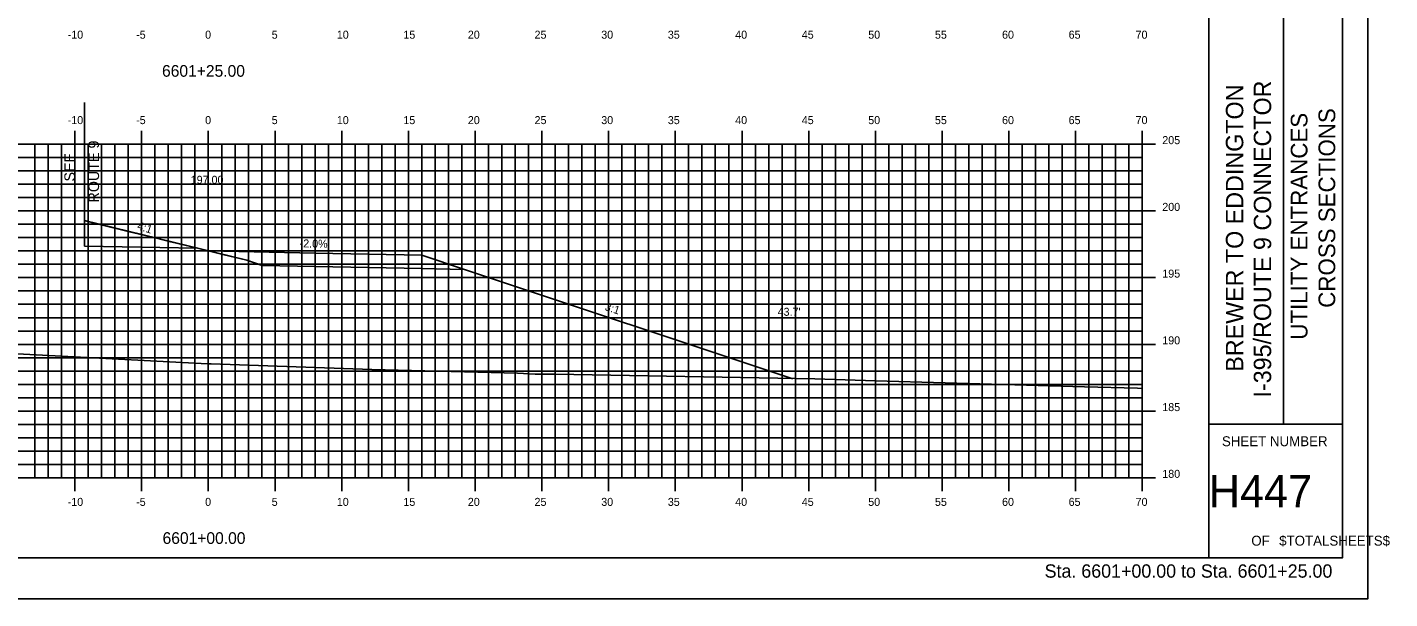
# Model space of a CAD drawing. Extents: x 1723518 to 1723690, y 459560 to 459670.
# Drawn here: x 1723587.4 to 1723689.5, y 459559.6 to 459602.4 of the extents above; entities that cross this region are included whole.
import ezdxf

# ---------------------------------------------------------------- set-up
doc = ezdxf.new("R2010")
doc.units = 0
for name, color, linetype in [('ANNOTATION', 7, 'Continuous'), ('BORDER', 7, 'Continuous'), ('D_Roadway_Centerline', 7, 'Continuous'), ('D_Roadway_Centerline_Text', 7, 'Continuous'), ('D_Roadway_Drive_Gravel', 7, 'Continuous'), ('D_Roadway_Edge_Shoulder', 7, 'Continuous'), ('D_Roadway_SlopeLines', 7, 'Continuous'), ('D_Roadway_SubGrade', 7, 'Continuous'), ('D_Text_Standard', 7, 'Continuous'), ('H_V ANNOTATION', 7, 'Continuous'), ('HIGHWAY_TITLE', 7, 'Continuous'), ('MAJOR', 7, 'Continuous'), ('MINOR', 7, 'Continuous'), ('PLOT BOUNDARY', 7, 'Continuous'), ('S_Roadway_Centerline', 7, 'Continuous')]:
    doc.layers.add(name, color=color, linetype=linetype)

msp = doc.modelspace()

# ---------------------------------------------------------------- linework, layer by layer
msp.add_lwpolyline([(1723600.95, 459585.61), (1723600.96, 459585.61), (1723608.96, 459585.45), (1723616.96, 459585.29), (1723620.15, 459584.23), (1723644.69, 459576.05), (1723644.72, 459576.05), (1723644.76, 459576.05), (1723644.77, 459576.04), (1723644.78, 459576.04)])
at = {"layer": 'BORDER'}
for p, q in [((1723675.96, 459562.61), (1723675.96, 459667.61)), ((1723681.55, 459572.62), (1723681.55, 459607.62)), ((1723675.96, 459572.62), (1723685.96, 459572.62))]:
    msp.add_line(p, q, dxfattribs=at)
msp.add_lwpolyline([(1723525.96, 459562.61), (1723685.96, 459562.61), (1723685.96, 459667.61), (1723525.96, 459667.61)], close=True, dxfattribs=at)
at = {"layer": 'D_Roadway_Centerline'}
msp.add_lwpolyline([(1723591.67, 459587.88), (1723592.32, 459587.72), (1723592.63, 459587.64), (1723595.06, 459587.05), (1723597, 459586.58), (1723598.15, 459586.3), (1723600.16, 459585.81), (1723602.05, 459585.35), (1723603.85, 459584.91), (1723603.97, 459584.87), (1723603.98, 459584.86), (1723605, 459584.53)], dxfattribs=at)
at = {"layer": 'D_Roadway_Drive_Gravel'}
msp.add_lwpolyline([(1723600.96, 459585.61), (1723608.96, 459585.45), (1723616.96, 459585.29), (1723620.15, 459584.23), (1723616.96, 459584.29), (1723608.96, 459584.45), (1723605, 459584.53)], dxfattribs=at)
at = {"layer": 'D_Roadway_Edge_Shoulder'}
msp.add_line((1723591.67, 459587.88), (1723591.67, 459587.63), dxfattribs=at)
msp.add_line((1723591.67, 459587.88), (1723591.67, 459587.63), dxfattribs=at)
at = {"layer": 'D_Roadway_SlopeLines'}
for points in [[(1723591.67, 459587.88), (1723603.85, 459584.91), (1723605, 459584.53)], [(1723591.67, 459587.88), (1723603.85, 459584.91), (1723605, 459584.53)], [(1723591.67, 459587.88), (1723603.85, 459584.91), (1723605, 459584.53)], [(1723591.67, 459587.88), (1723603.85, 459584.91), (1723605, 459584.53)], [(1723591.67, 459587.88), (1723603.85, 459584.91), (1723605, 459584.53)], [(1723591.67, 459587.88), (1723603.85, 459584.91), (1723605, 459584.53)], [(1723591.67, 459587.88), (1723603.85, 459584.91), (1723605, 459584.53)], [(1723616.96, 459585.29), (1723620.15, 459584.23), (1723644.69, 459576.05)]]:
    msp.add_lwpolyline(points, dxfattribs=at)
at = {"layer": 'D_Roadway_SubGrade'}
msp.add_line((1723591.67, 459596.74), (1723591.67, 459585.96), dxfattribs=at)
msp.add_lwpolyline([(1723591.67, 459587.63), (1723591.67, 459587.88), (1723600.16, 459585.81), (1723591.67, 459585.96)], dxfattribs=at)
msp.add_lwpolyline([(1723591.67, 459587.63), (1723591.67, 459587.88), (1723600.16, 459585.81), (1723591.67, 459585.96)], dxfattribs=at)
msp.add_lwpolyline([(1723591.67, 459587.63), (1723591.67, 459587.88), (1723600.16, 459585.81), (1723591.67, 459585.96)], dxfattribs=at)
msp.add_lwpolyline([(1723591.67, 459587.63), (1723591.67, 459587.88), (1723600.16, 459585.81), (1723591.67, 459585.96)], dxfattribs=at)
at = {"layer": 'MAJOR'}
for p, q in [((1723590.96, 459594.61), (1723590.96, 459593.61)), ((1723595.96, 459594.61), (1723595.96, 459593.61)), ((1723600.96, 459594.61), (1723600.96, 459593.61)), ((1723605.96, 459594.61), (1723605.96, 459593.61)), ((1723610.96, 459594.61), (1723610.96, 459593.61)), ((1723615.96, 459594.61), (1723615.96, 459593.61)), ((1723620.96, 459594.61), (1723620.96, 459593.61)), ((1723625.96, 459594.61), (1723625.96, 459593.61)), ((1723630.96, 459594.61), (1723630.96, 459593.61)), ((1723635.96, 459594.61), (1723635.96, 459593.61)), ((1723640.96, 459594.61), (1723640.96, 459593.61)), ((1723645.96, 459594.61), (1723645.96, 459593.61)), ((1723650.96, 459594.61), (1723650.96, 459593.61)), ((1723655.96, 459594.61), (1723655.96, 459593.61)), ((1723660.96, 459594.61), (1723660.96, 459593.61)), ((1723665.96, 459594.61), (1723665.96, 459593.61)), ((1723670.96, 459594.61), (1723670.96, 459593.61)), ((1723530.96, 459593.61), (1723670.96, 459593.61)), ((1723530.96, 459593.61), (1723670.96, 459593.61)), ((1723590.96, 459568.61), (1723590.96, 459593.61)), ((1723595.96, 459568.61), (1723595.96, 459593.61)), ((1723600.96, 459568.61), (1723600.96, 459593.61)), ((1723605.96, 459568.61), (1723605.96, 459593.61)), ((1723610.96, 459568.61), (1723610.96, 459593.61)), ((1723615.96, 459568.61), (1723615.96, 459593.61)), ((1723620.96, 459568.61), (1723620.96, 459593.61)), ((1723625.96, 459568.61), (1723625.96, 459593.61)), ((1723630.96, 459568.61), (1723630.96, 459593.61)), ((1723635.96, 459568.61), (1723635.96, 459593.61)), ((1723640.96, 459568.61), (1723640.96, 459593.61)), ((1723645.96, 459568.61), (1723645.96, 459593.61)), ((1723650.96, 459568.61), (1723650.96, 459593.61)), ((1723655.96, 459568.61), (1723655.96, 459593.61)), ((1723660.96, 459568.61), (1723660.96, 459593.61)), ((1723665.96, 459568.61), (1723665.96, 459593.61)), ((1723671.96, 459593.61), (1723669.96, 459593.61)), ((1723670.96, 459568.61), (1723670.96, 459593.61)), ((1723670.96, 459568.61), (1723670.96, 459593.61)), ((1723530.96, 459588.61), (1723670.96, 459588.61)), ((1723671.96, 459588.61), (1723669.96, 459588.61)), ((1723530.96, 459583.61), (1723670.96, 459583.61)), ((1723671.96, 459583.61), (1723669.96, 459583.61)), ((1723530.96, 459578.61), (1723670.96, 459578.61)), ((1723671.96, 459578.61), (1723669.96, 459578.61)), ((1723530.96, 459573.61), (1723670.96, 459573.61)), ((1723671.96, 459573.61), (1723669.96, 459573.61)), ((1723530.96, 459568.61), (1723670.96, 459568.61)), ((1723530.96, 459568.61), (1723670.96, 459568.61)), ((1723590.96, 459567.61), (1723590.96, 459568.61)), ((1723595.96, 459567.61), (1723595.96, 459568.61)), ((1723600.96, 459567.61), (1723600.96, 459568.61)), ((1723605.96, 459567.61), (1723605.96, 459568.61)), ((1723610.96, 459567.61), (1723610.96, 459568.61)), ((1723615.96, 459567.61), (1723615.96, 459568.61)), ((1723620.96, 459567.61), (1723620.96, 459568.61)), ((1723625.96, 459567.61), (1723625.96, 459568.61)), ((1723630.96, 459567.61), (1723630.96, 459568.61)), ((1723635.96, 459567.61), (1723635.96, 459568.61)), ((1723640.96, 459567.61), (1723640.96, 459568.61)), ((1723645.96, 459567.61), (1723645.96, 459568.61)), ((1723650.96, 459567.61), (1723650.96, 459568.61)), ((1723655.96, 459567.61), (1723655.96, 459568.61)), ((1723660.96, 459567.61), (1723660.96, 459568.61)), ((1723665.96, 459567.61), (1723665.96, 459568.61)), ((1723671.96, 459568.61), (1723669.96, 459568.61)), ((1723670.96, 459567.61), (1723670.96, 459568.61))]:
    msp.add_line(p, q, dxfattribs=at)
at = {"layer": 'MINOR'}
for p, q in [((1723587.96, 459568.61), (1723587.96, 459593.61)), ((1723588.96, 459568.61), (1723588.96, 459593.61)), ((1723589.96, 459568.61), (1723589.96, 459593.61)), ((1723591.96, 459568.61), (1723591.96, 459593.61)), ((1723592.96, 459568.61), (1723592.96, 459593.61)), ((1723593.96, 459568.61), (1723593.96, 459593.61)), ((1723594.96, 459568.61), (1723594.96, 459593.61)), ((1723596.96, 459568.61), (1723596.96, 459593.61)), ((1723597.96, 459568.61), (1723597.96, 459593.61)), ((1723598.96, 459568.61), (1723598.96, 459593.61)), ((1723599.96, 459568.61), (1723599.96, 459593.61)), ((1723601.96, 459568.61), (1723601.96, 459593.61)), ((1723602.96, 459568.61), (1723602.96, 459593.61)), ((1723603.96, 459568.61), (1723603.96, 459593.61)), ((1723604.96, 459568.61), (1723604.96, 459593.61)), ((1723606.96, 459568.61), (1723606.96, 459593.61)), ((1723607.96, 459568.61), (1723607.96, 459593.61)), ((1723608.96, 459568.61), (1723608.96, 459593.61)), ((1723609.96, 459568.61), (1723609.96, 459593.61)), ((1723611.96, 459568.61), (1723611.96, 459593.61)), ((1723612.96, 459568.61), (1723612.96, 459593.61)), ((1723613.96, 459568.61), (1723613.96, 459593.61)), ((1723614.96, 459568.61), (1723614.96, 459593.61)), ((1723616.96, 459568.61), (1723616.96, 459593.61)), ((1723617.96, 459568.61), (1723617.96, 459593.61)), ((1723618.96, 459568.61), (1723618.96, 459593.61)), ((1723619.96, 459568.61), (1723619.96, 459593.61)), ((1723621.96, 459568.61), (1723621.96, 459593.61)), ((1723622.96, 459568.61), (1723622.96, 459593.61)), ((1723623.96, 459568.61), (1723623.96, 459593.61)), ((1723624.96, 459568.61), (1723624.96, 459593.61)), ((1723626.96, 459568.61), (1723626.96, 459593.61)), ((1723627.96, 459568.61), (1723627.96, 459593.61)), ((1723628.96, 459568.61), (1723628.96, 459593.61)), ((1723629.96, 459568.61), (1723629.96, 459593.61)), ((1723631.96, 459568.61), (1723631.96, 459593.61)), ((1723632.96, 459568.61), (1723632.96, 459593.61)), ((1723633.96, 459568.61), (1723633.96, 459593.61)), ((1723634.96, 459568.61), (1723634.96, 459593.61)), ((1723636.96, 459568.61), (1723636.96, 459593.61)), ((1723637.96, 459568.61), (1723637.96, 459593.61)), ((1723638.96, 459568.61), (1723638.96, 459593.61)), ((1723639.96, 459568.61), (1723639.96, 459593.61)), ((1723641.96, 459568.61), (1723641.96, 459593.61)), ((1723642.96, 459568.61), (1723642.96, 459593.61)), ((1723643.96, 459568.61), (1723643.96, 459593.61)), ((1723644.96, 459568.61), (1723644.96, 459593.61)), ((1723646.96, 459568.61), (1723646.96, 459593.61)), ((1723647.96, 459568.61), (1723647.96, 459593.61)), ((1723648.96, 459568.61), (1723648.96, 459593.61)), ((1723649.96, 459568.61), (1723649.96, 459593.61)), ((1723651.96, 459568.61), (1723651.96, 459593.61)), ((1723652.96, 459568.61), (1723652.96, 459593.61)), ((1723653.96, 459568.61), (1723653.96, 459593.61)), ((1723654.96, 459568.61), (1723654.96, 459593.61)), ((1723656.96, 459568.61), (1723656.96, 459593.61)), ((1723657.96, 459568.61), (1723657.96, 459593.61)), ((1723658.96, 459568.61), (1723658.96, 459593.61)), ((1723659.96, 459568.61), (1723659.96, 459593.61)), ((1723661.96, 459568.61), (1723661.96, 459593.61)), ((1723662.96, 459568.61), (1723662.96, 459593.61)), ((1723663.96, 459568.61), (1723663.96, 459593.61)), ((1723664.96, 459568.61), (1723664.96, 459593.61)), ((1723666.96, 459568.61), (1723666.96, 459593.61)), ((1723667.96, 459568.61), (1723667.96, 459593.61)), ((1723668.96, 459568.61), (1723668.96, 459593.61)), ((1723669.96, 459568.61), (1723669.96, 459593.61)), ((1723530.96, 459592.61), (1723670.96, 459592.61)), ((1723670.96, 459592.61), (1723669.96, 459592.61)), ((1723530.96, 459591.61), (1723670.96, 459591.61)), ((1723670.96, 459591.61), (1723669.96, 459591.61)), ((1723530.96, 459590.61), (1723670.96, 459590.61)), ((1723670.96, 459590.61), (1723669.96, 459590.61)), ((1723530.96, 459589.61), (1723670.96, 459589.61)), ((1723670.96, 459589.61), (1723669.96, 459589.61)), ((1723530.96, 459587.61), (1723670.96, 459587.61)), ((1723670.96, 459587.61), (1723669.96, 459587.61)), ((1723530.96, 459586.61), (1723670.96, 459586.61)), ((1723670.96, 459586.61), (1723669.96, 459586.61)), ((1723530.96, 459585.61), (1723670.96, 459585.61)), ((1723670.96, 459585.61), (1723669.96, 459585.61)), ((1723530.96, 459584.61), (1723670.96, 459584.61)), ((1723670.96, 459584.61), (1723669.96, 459584.61)), ((1723530.96, 459582.61), (1723670.96, 459582.61)), ((1723670.96, 459582.61), (1723669.96, 459582.61)), ((1723530.96, 459581.61), (1723670.96, 459581.61)), ((1723670.96, 459581.61), (1723669.96, 459581.61)), ((1723530.96, 459580.61), (1723670.96, 459580.61)), ((1723670.96, 459580.61), (1723669.96, 459580.61)), ((1723530.96, 459579.61), (1723670.96, 459579.61)), ((1723670.96, 459579.61), (1723669.96, 459579.61)), ((1723530.96, 459577.61), (1723670.96, 459577.61)), ((1723670.96, 459577.61), (1723669.96, 459577.61)), ((1723530.96, 459576.61), (1723670.96, 459576.61)), ((1723670.96, 459576.61), (1723669.96, 459576.61)), ((1723530.96, 459575.61), (1723670.96, 459575.61)), ((1723670.96, 459575.61), (1723669.96, 459575.61)), ((1723530.96, 459574.61), (1723670.96, 459574.61)), ((1723670.96, 459574.61), (1723669.96, 459574.61)), ((1723530.96, 459572.61), (1723670.96, 459572.61)), ((1723670.96, 459572.61), (1723669.96, 459572.61)), ((1723530.96, 459571.61), (1723670.96, 459571.61)), ((1723670.96, 459571.61), (1723669.96, 459571.61)), ((1723530.96, 459570.61), (1723670.96, 459570.61)), ((1723670.96, 459570.61), (1723669.96, 459570.61)), ((1723530.96, 459569.61), (1723670.96, 459569.61)), ((1723670.96, 459569.61), (1723669.96, 459569.61))]:
    msp.add_line(p, q, dxfattribs=at)
at = {"layer": 'PLOT BOUNDARY'}
msp.add_lwpolyline([(1723517.87, 459559.55), (1723687.87, 459559.55), (1723687.87, 459669.55), (1723517.87, 459669.55)], close=True, dxfattribs=at)
at = {"layer": 'S_Roadway_Centerline'}
msp.add_lwpolyline([(1723530.96, 459578.87), (1723537.65, 459578.72), (1723543.16, 459578.68), (1723550.22, 459578.37), (1723555.1, 459578.15), (1723559.21, 459578.11), (1723575.11, 459578.31), (1723577.98, 459578.31), (1723580.88, 459578.21), (1723599.94, 459577.21), (1723600.89, 459577.15), (1723601.03, 459577.15), (1723601.18, 459577.14), (1723613.21, 459576.72), (1723624.14, 459576.44), (1723625.46, 459576.39), (1723626.96, 459576.39), (1723646.41, 459576.02), (1723650.96, 459575.89), (1723666.64, 459575.43), (1723670.6, 459575.34), (1723670.96, 459575.31)], dxfattribs=at)

# ---------------------------------------------------------------- texts
at = {"layer": 'ANNOTATION'}
for s, height, rotation, p in [('ROUTE 9', 0.8, 90, (1723592.77, 459589.24)), ('SEE', 0.8, 90, (1723590.97, 459590.81)), ('4:1', 0.6, 341.5651, (1723595.58, 459587.25)), ('-2.0%', 0.6, 358.8542, (1723607.8, 459585.88)), ('3:1', 0.6, 341.5651, (1723630.63, 459581.19))]:
    msp.add_text(s, height=height, rotation=rotation, dxfattribs=at).set_placement(p)
at = {"layer": 'BORDER'}
for s, p in [('UTILITY ENTRANCES', (1723683.34, 459578.96)), ('CROSS SECTIONS', (1723685.42, 459581.35))]:
    msp.add_text(s, height=1.25, rotation=90, dxfattribs=at).set_placement(p)
for s, height, p in [('SHEET NUMBER', 0.7453, (1723676.93, 459570.98)), ('H447', 2.419, (1723675.95, 459566.4)), ('OF', 0.745, (1723679.13, 459563.53)), ('$TOTALSHEETS$', 0.7453, (1723681.22, 459563.53))]:
    msp.add_text(s, height=height, dxfattribs=at).set_placement(p)
at = {"layer": 'D_Roadway_Centerline_Text'}
msp.add_text('197.00', height=0.6, dxfattribs=at).set_placement((1723599.64, 459590.64))
at = {"layer": 'D_Text_Standard'}
msp.add_text("43.7'", height=0.6, dxfattribs=at).set_placement((1723643.63, 459580.75))
at = {"layer": 'H_V ANNOTATION'}
for s, height, p in [('-10', 0.6, (1723590.42, 459601.51)), ('-5', 0.6, (1723595.55, 459601.51)), ('0', 0.6, (1723600.72, 459601.51)), ('5', 0.6, (1723605.71, 459601.51)), ('10', 0.6, (1723610.59, 459601.51)), ('15', 0.6, (1723615.58, 459601.51)), ('20', 0.6, (1723620.41, 459601.51)), ('25', 0.6, (1723625.41, 459601.51)), ('30', 0.6, (1723630.41, 459601.51)), ('35', 0.6, (1723635.4, 459601.51)), ('40', 0.6, (1723640.45, 459601.51)), ('45', 0.6, (1723645.44, 459601.51)), ('50', 0.6, (1723650.42, 459601.51)), ('55', 0.6, (1723655.42, 459601.51)), ('60', 0.6, (1723660.45, 459601.51)), ('65', 0.6, (1723665.44, 459601.51)), ('70', 0.6, (1723670.46, 459601.51)), ('6601+25.00', 0.875, (1723597.49, 459598.66)), ('-10', 0.6, (1723590.42, 459595.11)), ('-5', 0.6, (1723595.55, 459595.11)), ('0', 0.6, (1723600.72, 459595.11)), ('5', 0.6, (1723605.71, 459595.11)), ('10', 0.6, (1723610.59, 459595.11)), ('15', 0.6, (1723615.58, 459595.11)), ('20', 0.6, (1723620.41, 459595.11)), ('25', 0.6, (1723625.41, 459595.11)), ('30', 0.6, (1723630.41, 459595.11)), ('35', 0.6, (1723635.4, 459595.11)), ('40', 0.6, (1723640.45, 459595.11)), ('45', 0.6, (1723645.44, 459595.11)), ('50', 0.6, (1723650.42, 459595.11)), ('55', 0.6, (1723655.42, 459595.11)), ('60', 0.6, (1723660.45, 459595.11)), ('65', 0.6, (1723665.44, 459595.11)), ('70', 0.6, (1723670.46, 459595.11)), ('205', 0.6, (1723672.46, 459593.61)), ('200', 0.6, (1723672.46, 459588.61)), ('195', 0.6, (1723672.46, 459583.61)), ('190', 0.6, (1723672.46, 459578.61)), ('185', 0.6, (1723672.46, 459573.61)), ('180', 0.6, (1723672.46, 459568.61)), ('-10', 0.6, (1723590.42, 459566.51)), ('-5', 0.6, (1723595.55, 459566.51)), ('0', 0.6, (1723600.72, 459566.51)), ('5', 0.6, (1723605.71, 459566.51)), ('10', 0.6, (1723610.59, 459566.51)), ('15', 0.6, (1723615.58, 459566.51)), ('20', 0.6, (1723620.41, 459566.51)), ('25', 0.6, (1723625.41, 459566.51)), ('30', 0.6, (1723630.41, 459566.51)), ('35', 0.6, (1723635.4, 459566.51)), ('40', 0.6, (1723640.45, 459566.51)), ('45', 0.6, (1723645.44, 459566.51)), ('50', 0.6, (1723650.42, 459566.51)), ('55', 0.6, (1723655.42, 459566.51)), ('60', 0.6, (1723660.45, 459566.51)), ('65', 0.6, (1723665.44, 459566.51)), ('70', 0.6, (1723670.46, 459566.51)), ('6601+00.00', 0.875, (1723597.53, 459563.66)), ('Sta. 6601+00.00 to Sta. 6601+25.00', 1.0002, (1723663.64, 459561.13))]:
    msp.add_text(s, height=height, dxfattribs=at).set_placement(p)
at = {"layer": 'HIGHWAY_TITLE'}
for s, p in [('BREWER TO EDDINGTON', (1723678.53, 459576.56)), ('I-395/ROUTE 9 CONNECTOR', (1723680.62, 459574.63))]:
    msp.add_text(s, height=1.3043, rotation=90, dxfattribs=at).set_placement(p)

doc.saveas('drawing.dxf')
